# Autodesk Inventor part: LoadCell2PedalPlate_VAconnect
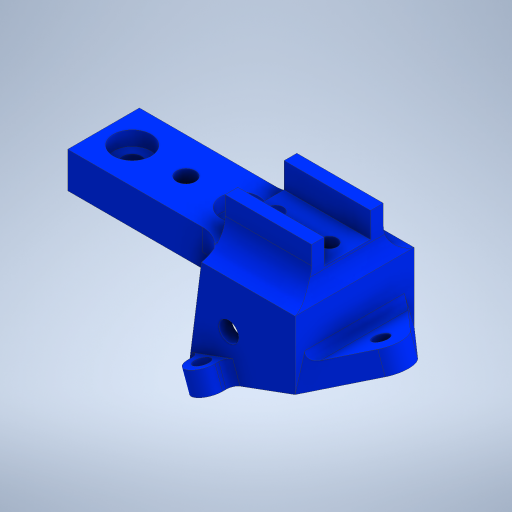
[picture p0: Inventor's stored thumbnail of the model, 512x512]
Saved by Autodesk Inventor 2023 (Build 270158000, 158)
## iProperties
Created: 2023-06
Part Number: LoadCell2PedalPlate_VAconnect
Material: Generic
Document SubType Name: Modeling
Designer: Admin
Density: 1 g/cm^3
Appearance: Default
Author: Admin
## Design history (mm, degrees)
sketch "Sketch1"
  geometry: L1 (0, 0)-(68, 0); L2 (68, 0)-(68, -20); L3 (68, -20)-(0, -20); L4 (0, -20)-(0, 0); L5 (60, -10)-(30, -10); L6 (30, -10)-(0, -10); C1 r 2.6 at (60, -10); C2 r 2.6 at (30, -10); C3 r 2.6 at (45, -10); C4 r 2.1 at (5, -10); C5 r 2.1 at (20, -10)
  constraints: 12 end point, 5 centre point, 3 equal radius, 3 parallel, 2 horizontal, 2 midpoint, 2 point on line, 1 perpendicular
  dimensions: "d0" = 20 distance between parallel lines of L3 L1; "d2" = 30 distance of L5.start L5.end; "d3" = 8 distance from line of L5.start L2; "d5" = 5.2 diameter of C1; "d10" = 60 distance from line of L4 L5.start; "d14" = 4.2 diameter of C4; "d16" = 5 distance from line of L4 C4.centre; "d17" = 15 distance of C5.centre C4.centre
extrude "Extrusion1" new body sketch "Sketch1" distance "d6" = 10; taper "d7" = 0 deg
sketch "Sketch2"
  geometry: C1 r 2.6 at (-60, 10) reference; C2 r 5.25 at (-60, 10); C3 r 2.6 at (-30, 10) reference; C4 r 5.25 at (-30, 10); 1 further point
  constraints: 2 centre point, 2 coincident, 1 equal radius
  dimensions: "d18" = 10.5 diameter of C2
extrude "Extrusion2" cut sketch "Sketch2" distance "d19" = 4; taper "d20" = 0 deg
chamfer "Chamfer2" distance "d21" = 2; stored, may be unused: second distance "d22" = 2, angle "d23" = 45 deg
sketch "Sketch3"
  geometry: L1 (0, 20)-(-68, 20) reference; L2 (0, 0)-(0, 20) reference; L3 (-24.1, 20)-(0, 20); L4 (0, 20)-(0, 0); L5 (0, 0)-(-24.1, 0); L6 (-24.1, 0)-(-24.1, 20); C1 r 2.1 at (-5, 10); C2 r 2.1 at (-5, 10) reference; C3 r 4.1 at (-20, 10) reference; C4 r 2.1 at (-20, 10); C5 r 2.1 at (-20, 10) reference; 1 further point
  constraints: 8 end point, 4 concentric, 2 centre point, 2 parallel, 1 horizontal, 1 perpendicular, 1 point on line, 1 tangent
extrude "Extrusion3" join sketch "Sketch3" distance "d24" = 4; taper "d25" = 0 deg
sketch "Sketch4"
  geometry: L1 (-24.1, 20)-(-24.1, 0) reference; L2 (-24.1, 20)-(0, 20); L3 (0, 20)-(0, 16.45); L4 (0, 16.45)-(-24.1, 16.45); L5 (-24.1, 16.45)-(-24.1, 20); L6 (0, 0)-(-24.1, 0); L7 (-24.1, 0)-(-24.1, 3.55); L8 (-24.1, 3.55)-(0, 3.55); L9 (0, 3.55)-(0, 0); 3 further points
  constraints: 16 end point, 4 parallel, 2 collinear, 2 horizontal, 2 perpendicular, 1 point on line
  dimensions: "d26" = 12.9 distance between parallel lines of L8 L4
extrude "Extrusion4" join sketch "Sketch4" distance "d27" = 7; taper "d28" = 0 deg
fillet "Fillet1" dims "d29" = 0.6
sketch "Sketch5"
  geometry: L1 (0, 0)-(68, 0) reference; L2 (0, 4)-(68, 4); L3 (68, 0)-(68, 10) reference; L4 (22.1, 14)-(22.1, 2) reference; L5 (1.5, 0)-(1.5, 4); L6 (1.5, 4)-(0, 4); L7 (1.5, 4)-(84.489, 4); L8 (84.489, 4)-(84.489, -38.399); L9 (84.489, -38.399)-(1.5, -38.399); L10 (1.5, -38.399)-(1.5, 4); L11 (70.6, 4)-(68, 4); L12 (70.6, 4)-(-31.161, 4); L13 (84.489, -38.399)-(-31.161, 4); L14 (24.1, 8)-(24.1, 4); L15 (24.1, 8)-(-2, 8); L16 (1.5, -7.974)-(1.5, 4); L17 (24.1, 4)-(1.5, 4); L18 (24.1, 10.6)-(24.1, 21) reference; L19 (-2, -10.951)-(-2, 8); L20 (-2, -10.951)-(22.723, -20.015); L21 (1.5, -7.974)-(24.1, -16.26); L22 (22.723, -20.015)-(24.1, -16.26); C1 r 3 at (16, -4); 3 further points; 1 other entity
  constraints: 28 end point, 8 point on line, 4 collinear, 3 vertical, 2 horizontal, 2 perpendicular, 1 centre point, 1 parallel, 1 vertical alignment, 2 other
  dimensions: "d45" = 4 distance between parallel lines of L1 L2; "d60" = 6 diameter of C1; "d62" = 8 distance of point (16, 4) C1.centre; "d76" = 2.6 distance of L2.end L11.start; "d84" = 42.39919 distance between parallel lines of L7 L9; "d89" = 20.1339 deg angle of L12 L13; "d94" = 4 distance between parallel lines of L17 L15; "d102" = 1.5 distance from line of L1.start L16; "d108" = 2 distance from line of L1.start L19; "d162" = 4 distance between parallel lines of L13 L20
extrude "Extrusion5" join sketch "Sketch5" distance "d96" = 3.1; taper "d97" = 0 deg
workplane "Work Plane1"
sketch "Sketch6"
  geometry: L1 (-2, -10.951)-(22.723, -20.015) reference; L2 (0, 8)-(24.1, 8) reference; L3 (-2, 8)-(-2, -10.951) reference; L4 (24.1, 8)-(-2, 8); L5 (-2, 8)-(-2, -10.951); L6 (-2, -10.951)-(22.723, -20.015); L7 (22.723, -20.015)-(27.364, -17.2) reference; L8 (22.723, -20.015)-(27.364, -17.2); L9 (27.364, -17.2)-(24.1, 8); L10 (0, 21)-(24.1, 21) reference; L11 (0, 21)-(0, -17.744); L12 (1.5, 4)-(24.1, 4) reference; C1 r 2.75 at (16.5, -5); 2 further points
  constraints: 12 end point, 2 collinear, 1 centre point, 1 perpendicular, 1 vertical
  dimensions: "d109" = 16.5 distance from line of L11 C1.centre; "d110" = 9 distance from line of C1.centre L12; "d111" = 5.5 diameter of C1
extrude "Extrusion6" join sketch "Sketch6" distance "d112" = 3.5; taper "d113" = 0 deg
sketch "Sketch7"
  geometry: L1 (-24.1, 8)-(2, 8) reference; L2 (2, 8)-(2, -10.951); L3 (0, 0)-(0, 8) reference; L4 (0, 8)-(2, 8); L5 (0, 0)-(-1.5, 0) reference; L6 (2, 8)-(2, -10.951) reference; L7 (2, -10.951)-(-1.5, -12.234); L8 (2, -10.951)-(-22.723, -20.015) reference; L9 (-1.5, -7.974)-(-1.5, -12.234); L10 (-1.5, -7.974)-(0, -6.474); L11 (0, 8)-(0, 21) reference; L12 (0, -6.474)-(0, 8); L13 (0, 8)-(0, -6.474); 1 further point
  constraints: 14 end point, 2 collinear, 2 vertical, 1 point on line
  dimensions: "d174" = 45 deg angle of L9 L10
extrude "Extrusion7" join sketch "Sketch7" stored distance "d117" = 4; taper "d118" = 0 deg
mirror "Mirror1"
fillet "Fillet2" dims "d119" = 8
sketch "Sketch8"
  geometry: C1 r 2.1 at (-5, -10) reference; C2 r 4.1 at (-5, -10); 1 further point
  constraints: 1 centre point, 1 coincident
extrude "Extrusion8" cut sketch "Sketch8" stored distance "d171" = 10; taper "d172" = 0 deg
sketch "Sketch9"
  geometry: L1 (23.244, 16.6)-(56.999, 16.6); L2 (23.244, 19.853)-(23.244, 11.897); L3 (22.604, 6.6)-(22.604, 14.465) reference; L4 (26.332, 33.2)-(0, 33.2) reference; L5 (26.332, 0)-(0, 0) reference; L6 (8, 33.2)-(8, 36.2); L7 (0, 36.2)-(0, 33.2); L8 (13.761, 33.2)-(8.261, 33.2) reference; L9 (8, 33.2)-(0, 33.2); L10 (26.332, 33.2)-(40.261, 21.135); L11 (42.332, 16.6)-(38.432, 16.6); L12 (34.232, 16.6)-(26.332, 16.6); L13 (26.332, 33.2)-(26.332, 0) reference; L14 (26.332, 33.2)-(26.332, 16.6); L15 (25.996, 6.6)-(25.996, 26.6) reference; L16 (0, 26.6)-(0, 29.7) reference; C1 r 52 at (9.999, 16.6); C2 r 3.5 at (56.999, 16.6); C3 r 3.5 at (-13.501, 57.303); C4 r 3.5 at (-13.501, -24.103); C5 r 2.1 at (4, 36.2); A1 r 47 centre (9.999, 16.6) between (56.999, 16.6) and (-13.501, -24.103); A2 r 2.1 centre (36.332, 16.6) between (38.432, 16.6) and (34.232, 16.6); A3 r 4 centre (4, 36.2) between (8, 36.2) and (0, 36.2); A4 r 6 centre (36.332, 16.6) between (42.332, 16.6) and (40.261, 21.135); 5 further points; 1 other entity
  constraints: 18 end point, 9 centre point, 8 point on circle, 7 point on line, 4 coincident, 3 tangent, 3 vertical, 2 parallel, 1 collinear, 1 equal radius, 1 horizontal, 1 horizontal alignment, 1 midpoint, 1 perpendicular, 9 other
  dimensions: "d179" = 104 diameter of C1; "d180" = 94 diameter of A1; "d181" = 7 diameter of C2; "d182" = 360 deg dimension on A1.centre L1.end (derived); "d183" = 4.2 diameter of A2; "d184" = 3 distance from line of L4 C5.centre; "d186" = 10 distance from line of L14 A2.centre; "d187" = 4 radius of A3; "d188" = 6 radius of A4; "d194" = 4 horizontal distance of L4.end C5.centre
extrude "Extrusion9" join sketch "Sketch9" distance "d190" = 6; taper "d191" = 0 deg
mirror "Mirror2"
fillet "Fillet3" dims "d192" = 2
body "Solid1"
node "Image7"
